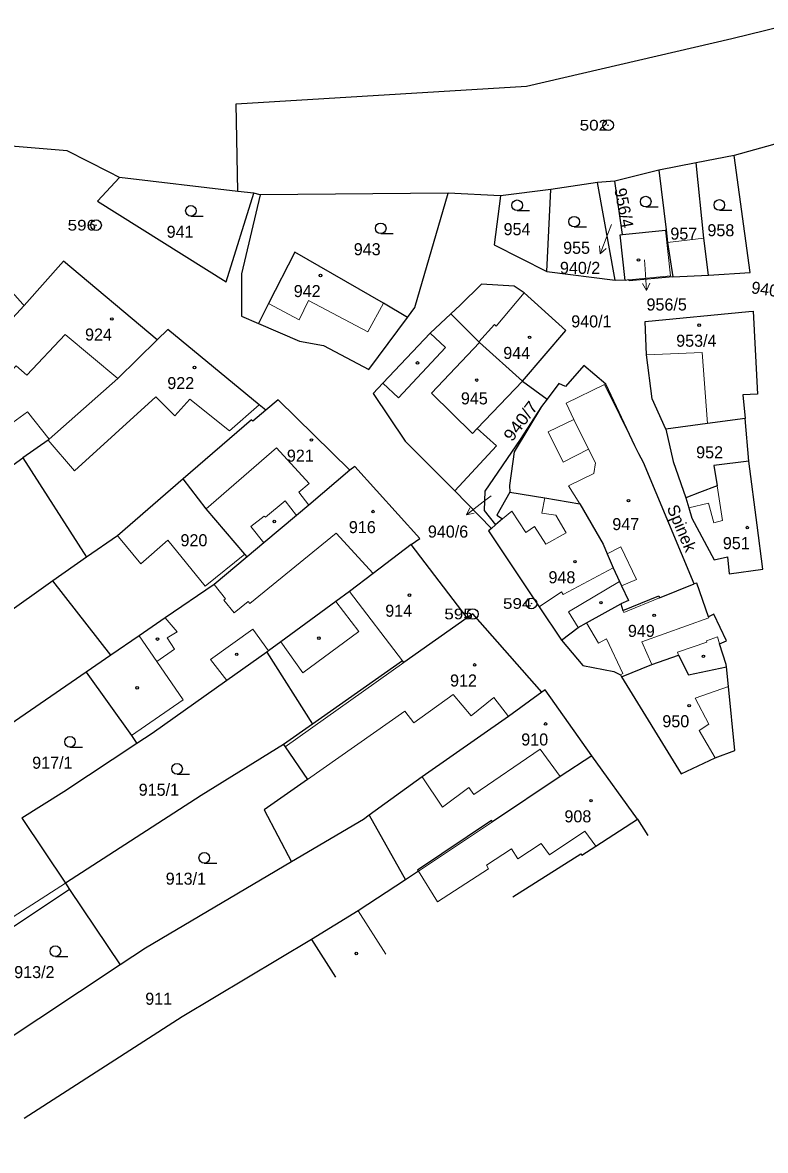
# Model space of a CAD drawing. Extents: x -546984 to -546090, y -1194931 to -1194069.
# Drawn here: x -546863 to -546758.1, y -1194927.6 to -1194768.4 of the extents above; entities that cross this region are included whole.
import ezdxf
from ezdxf.enums import TextEntityAlignment as Align

# ---------------------------------------------------------------- set-up
doc = ezdxf.new("R2010")
doc.units = 0
doc.header["$LTSCALE"] = 0.68
for name, color, linetype, lineweight in [('1', 7, 'Continuous', 25), ('3', 7, 'Continuous', 25), ('4', 7, 'Continuous', 13), ('5', 7, 'Continuous', 25), ('7', 7, 'Continuous', 13), ('8', 7, 'Continuous', 25)]:
    doc.layers.add(name, color=color, linetype=linetype, lineweight=lineweight)
doc.layers.add('2', color=7, linetype='Continuous')

msp = doc.modelspace()

# ---------------------------------------------------------------- linework, layer by layer
at = {"layer": '1'}
for p, q in [((-546755.97, -1194785.28), (-546762.54, -1194787.1)), ((-546762.54, -1194787.1), (-546767.93, -1194788.16)), ((-546767.93, -1194788.16), (-546773.17, -1194789.19)), ((-546832.61, -1194792.18), (-546849.31, -1194790.22)), ((-546773.17, -1194789.19), (-546779.39, -1194790.74)), ((-546773.17, -1194789.19), (-546772.15, -1194797.63)), ((-546788.43, -1194791.94), (-546795.55, -1194792.82)), ((-546781.84, -1194790.92), (-546788.43, -1194791.94)), ((-546779.39, -1194790.74), (-546781.84, -1194790.92)), ((-546778.31, -1194798.29), (-546779.39, -1194790.74)), ((-546830.33, -1194792.45), (-546832.61, -1194792.18)), ((-546829.44, -1194792.66), (-546830.33, -1194792.45)), ((-546802.9, -1194792.46), (-546829.44, -1194792.66)), ((-546795.55, -1194792.82), (-546802.9, -1194792.46)), ((-546777.95, -1194804.75), (-546779.34, -1194804.71)), ((-546802.53, -1194809.46), (-546805.47, -1194812.18)), ((-546802.53, -1194809.46), (-546798.6, -1194813.43)), ((-546792.4, -1194818.96), (-546788.96, -1194821.51)), ((-546788.96, -1194821.51), (-546789.75, -1194822.57)), ((-546760.49, -1194830.28), (-546761.02, -1194824.23)), ((-546867.38, -1194832.99), (-546862.93, -1194829.81)), ((-546862.93, -1194829.81), (-546853.94, -1194843.83)), ((-546796.8, -1194839.78), (-546801.99, -1194834.44)), ((-546796.21, -1194839.25), (-546796.8, -1194839.78)), ((-546800.21, -1194852.39), (-546808.15, -1194842.06)), ((-546853.94, -1194843.83), (-546858.71, -1194847.16)), ((-546850.52, -1194857.67), (-546858.71, -1194847.16)), ((-546828.49, -1194857.22), (-546822.07, -1194867.39)), ((-546776.18, -1194880.82), (-546782.63, -1194871.87)), ((-546814.06, -1194880.27), (-546808.94, -1194889.38)), ((-546776.18, -1194880.82), (-546774.727, -1194883.117)), ((-546856.33, -1194890.73), (-546871.76, -1194900.97)), ((-546822.18, -1194897.8), (-546818.797, -1194903.122))]:
    msp.add_line(p, q, dxfattribs=at)
for points in [[(-546832.61, -1194792.18), (-546832.81, -1194779.81), (-546791.87, -1194777.31), (-546762.86, -1194770.59), (-546745.98, -1194766.47), (-546719.75, -1194757.14), (-546687.4, -1194741.31)], [(-546849.31, -1194790.22), (-546850.76, -1194789.48), (-546856.66, -1194786.46), (-546871.93, -1194785.19), (-546918.16, -1194778.78)], [(-546766.16, -1194804), (-546760.3, -1194803.64), (-546762.54, -1194787.1)], [(-546766.16, -1194804), (-546766.81, -1194798.79), (-546767.93, -1194788.16)], [(-546849.31, -1194790.22), (-546852.41, -1194793.59), (-546834.25, -1194804.94), (-546830.33, -1194792.45)], [(-546795.55, -1194792.82), (-546796.44, -1194799.72), (-546788.97, -1194803.49), (-546788.43, -1194791.94)], [(-546788.97, -1194803.49), (-546779.34, -1194804.71), (-546781.84, -1194790.92)], [(-546829.44, -1194792.66), (-546832.06, -1194803.82), (-546832.1, -1194809.78), (-546829.7, -1194810.82)], [(-546808.65, -1194809.98), (-546807.6, -1194808.57), (-546802.9, -1194792.46)], [(-546862.75, -1194808.31), (-546862.92, -1194808.13), (-546872.08, -1194797.92), (-546876.44, -1194801.8)], [(-546777.95, -1194804.75), (-546778.64, -1194798.33), (-546778.31, -1194798.29)], [(-546778.31, -1194798.29), (-546772.22, -1194797.64), (-546772.15, -1194797.63)], [(-546772.15, -1194797.63), (-546771.94, -1194799.41), (-546771.19, -1194804.27), (-546766.16, -1194804)], [(-546808.65, -1194809.98), (-546812.03, -1194807.95), (-546824.55, -1194800.78), (-546828.26, -1194808.01), (-546829.7, -1194810.82)], [(-546843.98, -1194813.13), (-546857.22, -1194802.02), (-546862.75, -1194808.31)], [(-546771.19, -1194804.27), (-546777.38, -1194804.8), (-546777.4, -1194804.69), (-546777.95, -1194804.75)], [(-546792.4, -1194818.96), (-546786.33, -1194811.81), (-546792.2, -1194806.49), (-546793.59, -1194805.57), (-546798.19, -1194805.3), (-546801.22, -1194808.24), (-546802.53, -1194809.46)], [(-546862.75, -1194808.31), (-546867.13, -1194812.99), (-546867.26, -1194812.84), (-546871.25, -1194816.74), (-546871.41, -1194816.9), (-546875.33, -1194820), (-546879.29, -1194822.85)], [(-546772.21, -1194825.77), (-546774.14, -1194821.46), (-546774.91, -1194815.24), (-546775.12, -1194810.54), (-546760.49, -1194809.16), (-546759.89, -1194809.1), (-546759.26, -1194820.81), (-546761.32, -1194820.89), (-546761.02, -1194824.23)], [(-546829.7, -1194810.82), (-546823.91, -1194813.32), (-546820.49, -1194813.94), (-546814.11, -1194817.33), (-546808.65, -1194809.98)], [(-546828.64, -1194823.09), (-546829.58, -1194822.32), (-546842.47, -1194811.67), (-546843.98, -1194813.13)], [(-546805.47, -1194812.18), (-546812.12, -1194819.27), (-546813.48, -1194820.73), (-546808.98, -1194827.44), (-546801.99, -1194834.44)], [(-546843.98, -1194813.13), (-546849.53, -1194818.59), (-546859.21, -1194827.17), (-546859.37, -1194827.29), (-546862.93, -1194829.81)], [(-546798.6, -1194813.43), (-546798.51, -1194813.51), (-546792.4, -1194818.96)], [(-546768.2, -1194847.57), (-546775.37, -1194830.45), (-546776, -1194829.25), (-546776.55, -1194828.09), (-546780.68, -1194819.4), (-546783.77, -1194816.76), (-546786.35, -1194819.74), (-546787.3, -1194819.29), (-546788.96, -1194821.51)], [(-546801.99, -1194834.44), (-546796.07, -1194828.12), (-546798.8, -1194825.65), (-546792.4, -1194818.96)], [(-546816.8, -1194831.55), (-546826.89, -1194821.6), (-546828.64, -1194823.09)], [(-546828.64, -1194823.09), (-546830.47, -1194824.65), (-546830.68, -1194824.46), (-546840.3, -1194832.77)], [(-546789.75, -1194822.57), (-546792.74, -1194827.23), (-546797.75, -1194834.53), (-546797.85, -1194837.25), (-546796.21, -1194839.25)], [(-546789.75, -1194822.57), (-546793.6, -1194828.95), (-546794.27, -1194833.73), (-546794.19, -1194834.66)], [(-546761.02, -1194824.23), (-546766.33, -1194824.96), (-546772.21, -1194825.77)], [(-546772.21, -1194825.77), (-546771.15, -1194830.3), (-546769.36, -1194835.46)], [(-546816.8, -1194831.55), (-546822.57, -1194836.5), (-546824.3, -1194837.95), (-546828.92, -1194841.8), (-546831.28, -1194843.78)], [(-546808.15, -1194842.06), (-546806.92, -1194841.17), (-546816.08, -1194831.02), (-546816.8, -1194831.55)], [(-546760.49, -1194830.28), (-546765.43, -1194830.87), (-546764.97, -1194833.74), (-546767.43, -1194834.71), (-546769.36, -1194835.46)], [(-546769.36, -1194835.46), (-546768.94, -1194836.87), (-546768.51, -1194838.33), (-546765.37, -1194844.19), (-546763.49, -1194843.79), (-546763.24, -1194846.16), (-546758.49, -1194845.5), (-546759.3, -1194839.29), (-546760.49, -1194830.28)], [(-546840.3, -1194832.77), (-546849.58, -1194840.8), (-546853.94, -1194843.83)], [(-546831.28, -1194843.78), (-546831.61, -1194843.39), (-546837.08, -1194836.99), (-546840.3, -1194832.77)], [(-546794.19, -1194834.66), (-546796.04, -1194837.92), (-546795.26, -1194838.4), (-546796.21, -1194839.25)], [(-546794.19, -1194834.66), (-546789.29, -1194835.46), (-546784.35, -1194836.31), (-546781.05, -1194841.99), (-546780.46, -1194843.37), (-546779.62, -1194845.35), (-546778.73, -1194847.26), (-546778.43, -1194847.89), (-546777.45, -1194849.96), (-546778.54, -1194850.42)], [(-546796.8, -1194839.78), (-546797.2, -1194840.13), (-546790.06, -1194850.86), (-546786.94, -1194855.56)], [(-546808.15, -1194842.06), (-546813.5, -1194846.13), (-546816.86, -1194848.69), (-546818.77, -1194850.09), (-546826.53, -1194855.78), (-546828.26, -1194857.05), (-546828.49, -1194857.22)], [(-546831.28, -1194843.78), (-546835.95, -1194847.68), (-546842.83, -1194852.4), (-546846.54, -1194854.95), (-546850.52, -1194857.67), (-546854.01, -1194860.05)], [(-546858.71, -1194847.16), (-546880.57, -1194862.76), (-546887.59, -1194867.38)], [(-546778.54, -1194850.42), (-546778.25, -1194851.36), (-546773.19, -1194849.29), (-546773.09, -1194849.57), (-546768.2, -1194847.57)], [(-546763.65, -1194859.31), (-546763.68, -1194858.98), (-546764.6, -1194856.06), (-546763.64, -1194855.62), (-546765.42, -1194851.86), (-546766.19, -1194852.24), (-546767.8, -1194847.48), (-546768.2, -1194847.57)], [(-546786.94, -1194855.56), (-546784.55, -1194853.76), (-546783.37, -1194853.1), (-546778.54, -1194850.42)], [(-546800.21, -1194852.39), (-546809.15, -1194858.72), (-546809.35, -1194858.46), (-546822.07, -1194867.39), (-546826.16, -1194870.26)], [(-546789.69, -1194862.91), (-546799.44, -1194851.85), (-546800.21, -1194852.39)], [(-546786.94, -1194855.56), (-546783.9, -1194859.14), (-546779.53, -1194859.99), (-546778.6, -1194860.46), (-546778.43, -1194860.73)], [(-546828.49, -1194857.22), (-546834.16, -1194861.24), (-546844.68, -1194868.72), (-546846.83, -1194870.13)], [(-546778.43, -1194860.73), (-546774.19, -1194858.98), (-546770.42, -1194857.66), (-546769, -1194860.44), (-546763.65, -1194859.31)], [(-546854.01, -1194860.05), (-546867.66, -1194869.41), (-546869.72, -1194870.76)], [(-546854.01, -1194860.05), (-546847.62, -1194869.01), (-546846.83, -1194870.13)], [(-546778.43, -1194860.73), (-546770.01, -1194874.44), (-546765.21, -1194872.18), (-546762.45, -1194871.11), (-546763.37, -1194862.09), (-546763.65, -1194859.31)], [(-546789.69, -1194862.91), (-546794.42, -1194866.31), (-546806.6, -1194874.86), (-546814.06, -1194880.27)], [(-546782.63, -1194871.87), (-546789.21, -1194862.57), (-546789.69, -1194862.91)], [(-546846.83, -1194870.13), (-546857.16, -1194876.95), (-546863.06, -1194880.69), (-546863.02, -1194880.74), (-546856.92, -1194889.84)], [(-546826.16, -1194870.26), (-546837.76, -1194877.49), (-546856.92, -1194889.84)], [(-546826.16, -1194870.26), (-546825.92, -1194870.61), (-546822.78, -1194875.24), (-546828.89, -1194879.52), (-546825.02, -1194886.85)], [(-546782.63, -1194871.87), (-546787.11, -1194874.78), (-546796.67, -1194881.18), (-546796.79, -1194881.01), (-546807.22, -1194888.01), (-546807.11, -1194888.17), (-546808.94, -1194889.38)], [(-546814.06, -1194880.27), (-546814.86, -1194880.85), (-546825.02, -1194886.85)], [(-546793.772, -1194891.762), (-546784.17, -1194885.73), (-546784.06, -1194885.9), (-546782.06, -1194884.61), (-546776.18, -1194880.82)], [(-546825.02, -1194886.85), (-546845.64, -1194899.02), (-546849.19, -1194901.37)], [(-546856.92, -1194889.84), (-546856.33, -1194890.73), (-546849.19, -1194901.37)], [(-546808.94, -1194889.38), (-546815.63, -1194893.76), (-546822.18, -1194897.8)], [(-546822.18, -1194897.8), (-546840.47, -1194908.71), (-546862.762, -1194923.079)], [(-546849.19, -1194901.37), (-546878.1, -1194920.52), (-546872.7, -1194927.59)]]:
    msp.add_lwpolyline(points, dxfattribs=at)
at = {"layer": '3'}
for p, q in [((-546793.183, -1194794.9), (-546791.433, -1194794.9)), ((-546775.033, -1194794.38), (-546773.283, -1194794.38)), ((-546764.643, -1194794.85), (-546762.893, -1194794.85)), ((-546839.219, -1194795.686), (-546837.469, -1194795.686)), ((-546812.433, -1194798.15), (-546810.683, -1194798.15)), ((-546785.133, -1194797.21), (-546783.383, -1194797.21)), ((-546856.283, -1194870.65), (-546854.533, -1194870.65)), ((-546841.173, -1194874.46), (-546839.423, -1194874.46)), ((-546837.333, -1194887.02), (-546835.583, -1194887.02)), ((-546858.343, -1194900.21), (-546856.593, -1194900.21))]:
    msp.add_line(p, q, dxfattribs=at)
for centre in [(-546793.1829, -1194794.1498), (-546775.0329, -1194793.6298), (-546764.6429, -1194794.0998), (-546839.2188, -1194794.9363), (-546812.4329, -1194797.3998), (-546785.1329, -1194796.4598), (-546856.2829, -1194869.8998), (-546841.1729, -1194873.7098), (-546837.3329, -1194886.2698), (-546858.3429, -1194899.4598)]:
    msp.add_circle(centre, 0.75, dxfattribs=at)
at = {"layer": '4'}
for p, q in [((-546771.54, -1194804.09), (-546772.22, -1194797.64)), ((-546771.94, -1194799.41), (-546766.81, -1194798.79)), ((-546777.4, -1194804.69), (-546771.54, -1194804.09)), ((-546798.6, -1194813.43), (-546796.39, -1194811)), ((-546767.08, -1194814.95), (-546774.91, -1194815.24)), ((-546766.33, -1194824.96), (-546767.08, -1194814.95)), ((-546809.92, -1194821.33), (-546812.12, -1194819.27)), ((-546786.27, -1194822.1), (-546780.87, -1194819.46)), ((-546780.87, -1194819.46), (-546776.55, -1194828.09)), ((-546844.18, -1194821.2), (-546841.51, -1194823.86)), ((-546785.17, -1194824.37), (-546786.27, -1194822.1)), ((-546870.34, -1194829.15), (-546862.28, -1194823.3)), ((-546862.28, -1194823.3), (-546859.21, -1194827.17)), ((-546788.8, -1194826.13), (-546785.17, -1194824.37)), ((-546785.17, -1194824.37), (-546783.12, -1194828.59)), ((-546786.68, -1194830.43), (-546788.8, -1194826.13)), ((-546783.12, -1194828.59), (-546786.68, -1194830.43)), ((-546782.13, -1194830.52), (-546783.12, -1194828.59)), ((-546782.37, -1194832.01), (-546782.13, -1194830.52)), ((-546822.53, -1194833.43), (-546823.99, -1194834.66)), ((-546785.94, -1194833.74), (-546782.37, -1194832.01)), ((-546823.99, -1194834.66), (-546822.57, -1194836.5)), ((-546784.35, -1194836.31), (-546785.94, -1194833.74)), ((-546768.94, -1194836.87), (-546766.18, -1194836.21)), ((-546828.71, -1194838.2), (-546828.9, -1194838.02)), ((-546795.26, -1194838.4), (-546793.91, -1194837.33)), ((-546780.46, -1194843.37), (-546778.54, -1194842.36)), ((-546778.54, -1194842.36), (-546776.34, -1194846.96)), ((-546785.95, -1194851.57), (-546778.73, -1194847.26)), ((-546776.34, -1194846.96), (-546778.43, -1194847.89)), ((-546816.86, -1194848.69), (-546809.35, -1194858.46)), ((-546831.13, -1194850.1), (-546830.9, -1194850.39)), ((-546842.83, -1194852.4), (-546841.18, -1194854.37)), ((-546784.55, -1194853.76), (-546785.95, -1194851.57)), ((-546830.5, -1194853.99), (-546828.26, -1194857.05)), ((-546841.18, -1194854.37), (-546842.59, -1194855.24)), ((-546766.46, -1194855.64), (-546766.39, -1194855.82)), ((-546774.19, -1194858.98), (-546775.59, -1194855.76)), ((-546809.15, -1194858.72), (-546825.92, -1194870.61)), ((-546796.46, -1194863.64), (-546794.42, -1194866.31)), ((-546822.78, -1194875.24), (-546809.02, -1194865.58)), ((-546806.6, -1194874.86), (-546803.71, -1194879.13)), ((-546803.71, -1194879.13), (-546799.98, -1194876.36)), ((-546796.67, -1194881.18), (-546807.11, -1194888.17)), ((-546793.09, -1194886.4), (-546789.79, -1194884.26)), ((-546856.92, -1194889.84), (-546886.92, -1194909.18)), ((-546811.689, -1194899.896), (-546815.63, -1194893.76))]:
    msp.add_line(p, q, dxfattribs=at)
for points in [[(-546828.26, -1194808.01), (-546823.94, -1194810.34), (-546822.64, -1194807.59), (-546814.27, -1194812.02), (-546812.03, -1194807.95)], [(-546796.39, -1194811), (-546796.16, -1194811.22), (-546792.2, -1194806.49)], [(-546875.33, -1194820), (-546872.66, -1194823.19), (-546868.74, -1194819.98), (-546867.75, -1194820.92), (-546863.87, -1194816.82), (-546862.39, -1194818.15), (-546856.98, -1194812.37), (-546849.53, -1194818.59)], [(-546805.47, -1194812.18), (-546803.27, -1194814.24), (-546809.92, -1194821.33)], [(-546798.51, -1194813.51), (-546805.28, -1194820.66), (-546799.5, -1194826.38), (-546798.8, -1194825.65)], [(-546859.37, -1194827.29), (-546855.64, -1194831.66), (-546844.18, -1194821.2)], [(-546841.51, -1194823.86), (-546839.39, -1194821.54), (-546833.75, -1194825.98), (-546829.58, -1194822.32)], [(-546837.08, -1194836.99), (-546827.13, -1194828.39), (-546822.53, -1194833.43)], [(-546766.18, -1194836.21), (-546765.42, -1194838.99), (-546764.18, -1194838.66), (-546764.97, -1194833.74)], [(-546824.3, -1194837.95), (-546825.9, -1194835.87), (-546828.71, -1194838.2)], [(-546790.74, -1194839.5), (-546789.13, -1194842), (-546786.26, -1194840.4), (-546787.71, -1194837.89), (-546789.69, -1194837.6), (-546789.29, -1194835.46)], [(-546828.9, -1194838.02), (-546830.76, -1194839.49), (-546828.92, -1194841.8)], [(-546793.91, -1194837.33), (-546791.95, -1194840.34), (-546790.74, -1194839.5)], [(-546849.58, -1194840.8), (-546849.42, -1194840.95), (-546846.27, -1194844.75)], [(-546830.9, -1194850.39), (-546818.74, -1194840.44), (-546813.5, -1194846.13)], [(-546846.27, -1194844.75), (-546842.48, -1194841.45), (-546837.2, -1194847.94), (-546831.61, -1194843.39)], [(-546779.62, -1194845.35), (-546786.69, -1194849.12), (-546786.91, -1194848.7), (-546790.06, -1194850.86)], [(-546835.95, -1194847.68), (-546834.33, -1194849.71), (-546834.55, -1194849.89), (-546833.11, -1194851.71), (-546831.13, -1194850.1)], [(-546826.53, -1194855.78), (-546823.44, -1194860.16), (-546815.51, -1194854.32), (-546818.77, -1194850.09)], [(-546773.09, -1194849.57), (-546778.14, -1194851.63), (-546778.25, -1194851.36)], [(-546775.59, -1194855.76), (-546766.15, -1194852.38), (-546766.19, -1194852.24)], [(-546834.16, -1194861.24), (-546836.46, -1194858.26), (-546830.5, -1194853.99)], [(-546783.37, -1194853.1), (-546781.72, -1194855.97), (-546780.58, -1194855.37), (-546778.27, -1194860.26), (-546778.6, -1194860.46)], [(-546847.62, -1194869.01), (-546840.3, -1194863.96), (-546844.03, -1194858.56), (-546846.54, -1194854.95)], [(-546842.59, -1194855.24), (-546841.52, -1194856.81), (-546844.03, -1194858.56)], [(-546764.6, -1194856.06), (-546764.92, -1194855.06), (-546766.46, -1194855.64)], [(-546766.39, -1194855.82), (-546770.56, -1194857.26), (-546770.42, -1194857.66)], [(-546763.37, -1194862.09), (-546768.05, -1194863.74), (-546766.14, -1194867.4), (-546767.51, -1194868.31), (-546765.21, -1194872.18)], [(-546809.02, -1194865.58), (-546807.78, -1194867.22), (-546802.21, -1194863.23), (-546799.67, -1194866.23), (-546796.46, -1194863.64)], [(-546799.98, -1194876.36), (-546799.31, -1194877.32), (-546789.91, -1194870.94), (-546787.11, -1194874.78)], [(-546789.79, -1194884.26), (-546788.61, -1194885.87), (-546783.61, -1194882.52), (-546782.06, -1194884.61)], [(-546807.11, -1194888.17), (-546804.4, -1194892.5), (-546797.22, -1194887.81), (-546797.48, -1194887.32), (-546793.96, -1194885.02), (-546793.09, -1194886.4)]]:
    msp.add_lwpolyline(points, dxfattribs=at)
at = {"layer": '5'}
for centre in [(-546776.0468, -1194801.8692), (-546820.9268, -1194804.0592), (-546850.3768, -1194810.1992), (-546767.4868, -1194811.0692), (-546791.4268, -1194812.7992), (-546838.7068, -1194817.0492), (-546807.2468, -1194816.3992), (-546798.8868, -1194818.8292), (-546822.2068, -1194827.2992), (-546777.4668, -1194835.8592), (-546813.5168, -1194837.3892), (-546827.4568, -1194838.7892), (-546760.6968, -1194839.6492), (-546785.0168, -1194844.4692), (-546808.3768, -1194849.1892), (-546781.3468, -1194850.2592), (-546773.8368, -1194852.0392), (-546843.9368, -1194855.3992), (-546821.1568, -1194855.2592), (-546832.7568, -1194857.5492), (-546799.1768, -1194859.0392), (-546766.8868, -1194857.8392), (-546846.7968, -1194862.2792), (-546768.9068, -1194864.7892), (-546789.1668, -1194867.3692), (-546782.7468, -1194878.2192), (-546815.8768, -1194899.7892)]:
    msp.add_circle(centre, 0.175, dxfattribs=at)
at = {"layer": '7'}
for p, q in [((-546781.445, -1194801.002), (-546780.619, -1194800.246)), ((-546774.901, -1194806.174), (-546774.471, -1194805.14)), ((-546800.325, -1194837.858), (-546799.227, -1194837.636))]:
    msp.add_line(p, q, dxfattribs=at)
for points in [[(-546779.85, -1194796.84), (-546780.37, -1194798.2), (-546781.445, -1194801.002), (-546781.554, -1194799.887)], [(-546775.19, -1194801.87), (-546775.11, -1194803.18), (-546774.901, -1194806.174), (-546775.47, -1194805.21)], [(-546796.85, -1194835.15), (-546797.96, -1194836.01), (-546800.325, -1194837.858), (-546799.844, -1194836.846)]]:
    msp.add_lwpolyline(points, dxfattribs=at)
at = {"layer": '8'}
for centre, radius in [((-546780.34, -1194782.8398), 0.75), ((-546780.34, -1194782.8398), 0.03), ((-546852.6, -1194796.9598), 0.75), ((-546852.6, -1194796.9598), 0.03), ((-546791.16, -1194850.3698), 0.75), ((-546791.16, -1194850.3698), 0.03), ((-546799.44, -1194851.8498), 0.75), ((-546799.44, -1194851.8498), 0.03)]:
    msp.add_circle(centre, radius, dxfattribs=at)

# ---------------------------------------------------------------- texts
at = {"layer": '2'}
msp.add_text('956/4', height=1.7, rotation=281, dxfattribs=at).set_placement((-546778.9327, -1194794.6898), align=Align.CENTER)
for s, p in [('954', (-546795.09, -1194798.37)), ('956/5', (-546774.92, -1194809.003)), ('940/1', (-546785.544, -1194811.387)), ('953/4', (-546770.73, -1194814.12))]:
    msp.add_text(s, height=1.7, dxfattribs=at).set_placement(p)
for s, p in [('958', (-546764.429, -1194798.52)), ('941', (-546840.744, -1194798.736)), ('957', (-546769.659, -1194799)), ('943', (-546814.339, -1194801.2)), ('955', (-546784.789, -1194801)), ('942', (-546822.809, -1194807.11)), ('924', (-546852.259, -1194813.25)), ('944', (-546793.239, -1194815.85)), ('922', (-546840.649, -1194820.1)), ('945', (-546799.219, -1194822.26)), ('921', (-546823.779, -1194830.35)), ('952', (-546766.019, -1194829.87)), ('916', (-546815.029, -1194840.44)), ('940/6', (-546802.93, -1194841.07)), ('947', (-546777.849, -1194840.01)), ('920', (-546838.789, -1194842.29)), ('951', (-546762.249, -1194842.7)), ('948', (-546786.859, -1194847.52)), ('914', (-546809.889, -1194852.24)), ('949', (-546775.649, -1194855.09)), ('912', (-546800.749, -1194862.09)), ('950', (-546770.789, -1194867.84)), ('910', (-546790.699, -1194870.42)), ('917/1', (-546858.77, -1194873.7)), ('915/1', (-546843.74, -1194877.51)), ('908', (-546784.609, -1194881.27)), ('913/1', (-546839.93, -1194890.07)), ('913/2', (-546861.31, -1194903.26)), ('911', (-546843.759, -1194907.02))]:
    msp.add_text(s, height=1.7, dxfattribs=at).set_placement(p, align=Align.CENTER)
msp.add_text('940/2', height=1.7, dxfattribs=at).set_placement((-546781.449, -1194803.833), align=Align.RIGHT)
msp.add_text('940/3', height=1.7, rotation=352, dxfattribs=at).set_placement((-546754.5866, -1194807.3571), align=Align.RIGHT)
at = {"layer": '2', "width": 1.1}
msp.add_text('940/7', height=1.7, rotation=53, dxfattribs=at).set_placement((-546792.0049, -1194825.128), align=Align.CENTER)
at = {"layer": '7'}
msp.add_text('Spinek', height=1.7, rotation=293, dxfattribs=at).set_placement((-546770.7353, -1194840.0709), align=Align.CENTER)
at = {"layer": '8', "width": 1.2}
for s, p in [('502', (-546780.34, -1194783.59)), ('596', (-546852.6, -1194797.71)), ('594', (-546791.16, -1194851.12)), ('595', (-546799.44, -1194852.6))]:
    msp.add_text(s, height=1.5, dxfattribs=at).set_placement(p, align=Align.RIGHT)

doc.saveas('drawing.dxf')
